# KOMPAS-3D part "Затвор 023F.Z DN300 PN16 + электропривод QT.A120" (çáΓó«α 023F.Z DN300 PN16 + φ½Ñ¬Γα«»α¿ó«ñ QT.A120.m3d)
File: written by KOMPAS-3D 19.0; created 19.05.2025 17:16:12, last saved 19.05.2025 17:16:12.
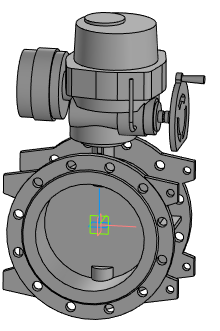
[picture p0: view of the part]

Document properties: Полное имя файла: Затвор 023F.Z DN300 PN16 + электропривод QT.A120.a3d

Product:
- Part/product: Затвор 023F.Z DN300 PN16 + электропривод QT.A120
    Масса: 223.947

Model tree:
1. Операция без истории:1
